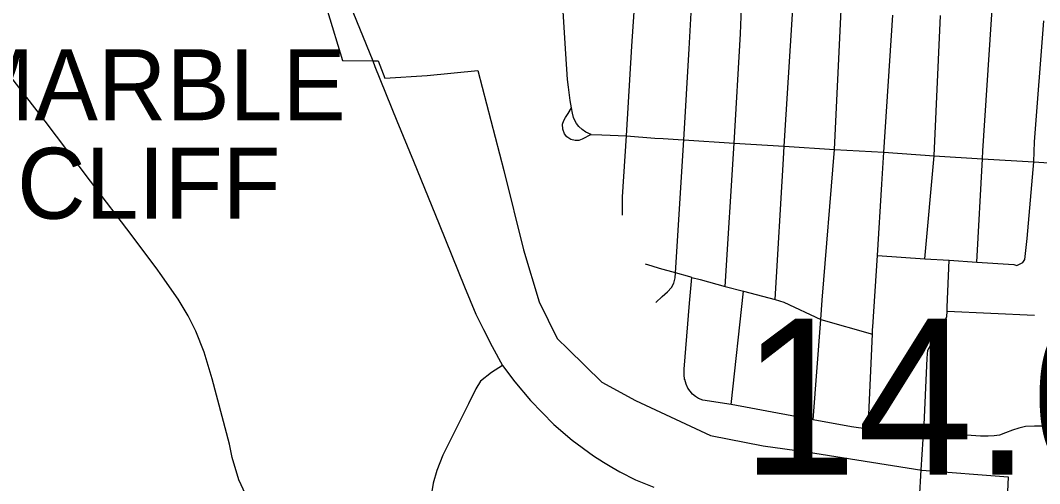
# Model space of a CAD drawing. Extents: x 1659811 to 1934326, y 644115 to 934867.
# Drawn here: x 1807811 to 1814994, y 720077 to 723342 of the extents above; entities that cross this region are included whole.
import ezdxf

# ---------------------------------------------------------------- set-up
doc = ezdxf.new("R2010")
doc.units = 0
for name, color, linetype in [('Default', 7, 'Continuous'), ('GM_X_City_Street', 7, 'Continuous'), ('GM_X_Corporation', 7, 'Continuous'), ('GM_X_Corporation_Text', 7, 'Continuous'), ('GM_X_US_Route', 7, 'Continuous')]:
    doc.layers.add(name, color=color, linetype=linetype)

msp = doc.modelspace()

# ---------------------------------------------------------------- linework, layer by layer
at = {"layer": 'GM_X_City_Street'}
for points in [[(1808795.1, 721558), (1808779, 721580.7), (1808599.2, 721824.2), (1808306, 722208.8), (1807985.2, 722632.1), (1807670.9, 723038.7), (1807377.6, 723432), (1806989.8, 723953.5), (1806147.3, 725108.1), (1805654.1, 725776.1), (1805409.9, 726117.9), (1805269.4, 726309.7), (1805131.2, 726507.4), (1805081.3, 726573.7), (1805021.7, 726645), (1804975, 726686.2)], [(1812486.9, 722499.7), (1812523.3, 723140.4), (1812553.7, 723692.4), (1812540.7, 723725.4), (1812553.7, 723943.3), (1812621.9, 725031.4)], [(1812778.9, 721467.3), (1812841.8, 722477.5), (1812886.3, 723247.8), (1812895.8, 723492.7), (1812895.8, 723524.6), (1812887.8, 723553.2), (1812849.6, 723594.6), (1812836.9, 723621.7), (1812836.9, 723674.2), (1812879, 724155.2), (1812932.6, 725012.8)], [(1811834.1, 722538.8), (1811795.9, 722553.5), (1811769.5, 722571.9), (1811746.4, 722595.2), (1811730.8, 722614.3), (1811718.7, 722637.3), (1811710, 722658.6), (1811701.3, 722688.1), (1811694.3, 722724.5), (1811684.8, 722777.5), (1811672.7, 722872.1), (1811667.4, 722925.9), (1811661.4, 722998), (1811651.8, 723140.4), (1811634.4, 723445), (1811630.1, 723571.7), (1811622.4, 723731.8)], [(1812081.5, 722527.5), (1812120.6, 723161.2), (1812144, 723507.5), (1812154.3, 723685.4)], [(1813129.6, 721374.4), (1813187.9, 722367.3), (1813194.6, 722454.3), (1813268.3, 723648.7)], [(1814552.2, 721638.8), (1814590.7, 722366.3), (1814593.6, 722422), (1814668.9, 723564.4)], [(1813398.7, 720526.3), (1813450.9, 721232.9), (1813462.2, 721369.8), (1813547.3, 722431.1), (1813594.8, 723416.9)], [(1813818.3, 721182), (1813850.4, 721683.9), (1813882.6, 722186.7), (1813897.1, 722412.4), (1813959, 723379.1)], [(1814186, 721662.3), (1814250.3, 722387), (1814294.3, 723376.9)], [(1814875, 721635.5), (1814888.6, 721655.9), (1814905.2, 721804.8), (1814953.4, 722345.2), (1814957.5, 722486.7), (1815023.8, 723337.6)], [(1811834.1, 722538.8), (1811769, 722504.1), (1811747.3, 722495.4), (1811720.4, 722494.5), (1811689.1, 722503.2), (1811663.1, 722521.4), (1811644.9, 722543.1), (1811632.7, 722576.1), (1811631.8, 722610), (1811641.4, 722636), (1811651.8, 722657.7), (1811670.9, 722685.5), (1811694.3, 722724.5)], [(1811834.1, 722538.8), (1811907.9, 722534.4), (1812081.5, 722527.5)], [(1812054.6, 721968.5), (1812054.6, 722099.5), (1812081.5, 722527.5)], [(1812081.5, 722527.5), (1812281.9, 722512.5), (1812341.5, 722508.8)], [(1812341.5, 722508.8), (1812445.6, 722502.3)], [(1812428.2, 721563.7), (1812486.9, 722499.7)], [(1812445.6, 722502.3), (1812486.9, 722499.7), (1812841.8, 722477.5), (1813194.6, 722454.3), (1813547.3, 722431.1), (1813897.1, 722412.4), (1814250.3, 722387), (1814590.7, 722366.3), (1814953.4, 722345.2), (1815345.5, 722319.7)], [(1813850.4, 721683.9), (1814186, 721662.3), (1814355.5, 721651.4), (1814552.2, 721638.8), (1814813.1, 721622), (1814833.4, 721614.4), (1814875, 721635.5)], [(1812428.2, 721563.7), (1812315.3, 721594.1), (1812263.3, 721609.7), (1812216.5, 721622.8)], [(1814172.9, 720390.5), (1814173, 720390.9), (1814178.2, 720440.4), (1814200.4, 720961.2), (1814207.1, 721017.6), (1814299.6, 721182.4), (1814340.1, 721253.6), (1814341.5, 721292.9), (1814342.5, 721319.9), (1814355.5, 721651.4)], [(1809957.5, 719201.3), (1809776.8, 719433.6), (1809579, 719687.3), (1809497.2, 719814.2), (1809436.9, 719925.9), (1809398.2, 720003.3), (1809351.5, 720103.2), (1809303.9, 720261.2), (1809284.4, 720354.3), (1809232.5, 720551.3), (1809163.3, 720815.3), (1809107, 721003.6), (1809048.6, 721150.8), (1808994.5, 721259), (1808923.1, 721378.1), (1808795.1, 721558)], [(1812290.2, 721352.8), (1812333.6, 721396.2), (1812371.8, 721428.3), (1812400.4, 721459.5), (1812416, 721489.9), (1812425.6, 721528.1), (1812428.2, 721563.7)], [(1812529.2, 721534.1), (1812428.2, 721563.7)], [(1812492.6, 720810.6), (1812492.4, 720811.1), (1812489, 720846.7), (1812489, 720884.9), (1812526.3, 721350.1), (1812543.7, 721529.8), (1812529.2, 721534.1)], [(1812543.7, 721529.8), (1812600.9, 721515.9), (1812778.9, 721467.3), (1812906.5, 721432.6), (1813129.6, 721374.4), (1813190.3, 721356.2), (1813450.9, 721232.9), (1813815, 721130.9)], [(1812819.7, 720634), (1812906.5, 721432.6)], [(1814341.5, 721292.9), (1814958, 721263.9)], [(1813785.8, 720462.1), (1813815, 721130.9), (1813817, 721161.8), (1813818.3, 721182)], [(1815022.8, 720483), (1814957.7, 720483), (1814894.3, 720479.1), (1814846.6, 720468.2), (1814803.2, 720453.4), (1814754.6, 720434.4), (1814710.3, 720419.6), (1814673.9, 720413.5), (1814630.5, 720410.9), (1814576.6, 720412.6), (1814178.2, 720440.4), (1813785.8, 720462.1), (1813668.6, 720478.6), (1813398.7, 720526.3), (1812957.7, 720609.7), (1812819.7, 720634), (1812620.9, 720666.1), (1812589.6, 720678.3), (1812569.7, 720690.4), (1812547.1, 720707.8), (1812530.6, 720727.8), (1812514.1, 720750.3), (1812502.8, 720779), (1812492.6, 720810.6)], [(1814158.2, 720174.8), (1814172.9, 720390.5)], [(1814147, 719955.1), (1814147.8, 719967.6), (1814158.2, 720174.8)]]:
    msp.add_lwpolyline(points, dxfattribs=at)
at = {"layer": 'GM_X_Corporation'}
msp.add_lwpolyline([(1809870.1, 723755.9), (1810081.5, 723059.9), (1810294.1, 723056.4), (1810333.2, 723055.8), (1810379.2, 722934.3), (1810677, 722954.2), (1811035.5, 722989), (1811218.4, 722284.4), (1811356.1, 721725), (1811467.7, 721357.8), (1811593.9, 721100.8), (1811670.5, 721025.1), (1811908.3, 720791.5), (1812145.7, 720663.2), (1812674, 720415.4), (1813045.6, 720344.3), (1813351.6, 720300.6), (1814163.1, 720172.6), (1814772.4, 720125.6), (1814739.6, 719391.6)], dxfattribs=at)
at = {"layer": 'GM_X_US_Route'}
for points in [[(1809423.7, 725672.5), (1809490.4, 725538.9), (1809558, 725396.9), (1809595.4, 725307.5), (1809632.7, 725192.1), (1809680.4, 724995), (1809767.2, 724626.1), (1809829.7, 724390), (1809924.4, 724074.9), (1810012.9, 723801.5), (1810133.6, 723453.4), (1810294.1, 723056.4), (1810309.8, 723017.5)], [(1810309.8, 723017.5), (1810464.3, 722633.1), (1810581.5, 722350.1), (1810762, 721904.8), (1810940.9, 721464.7), (1811021.6, 721271.1), (1811074, 721162.9), (1811135.7, 721044), (1811208, 720910.1)], [(1811208, 720910.1), (1811130.5, 720860), (1811054.1, 720798.3), (1811020.2, 720744.5), (1810968.6, 720639.8)], [(1811208, 720910.1), (1811295.4, 720794.9), (1811405.6, 720662.9), (1811569.7, 720493.6), (1811699, 720383.4), (1811851, 720274), (1811921.3, 720228), (1811978.6, 720194.2), (1812036.7, 720160.3), (1812146.1, 720104.8), (1812274.6, 720051.8)], [(1810968.6, 720639.8), (1810924.3, 720550.1), (1810787.6, 720277.5), (1810745.9, 720169), (1810720.8, 720079.6), (1810706.9, 719992.8), (1810697.3, 719915.5), (1810696.4, 719825.2), (1810700.8, 719760.1), (1810709.5, 719703.7), (1810717.3, 719656), (1810730.3, 719604.8), (1810745.1, 719554.4), (1810769.3, 719492.7), (1810798.9, 719428.5), (1810844.9, 719346.1), (1810903.9, 719262.7), (1811006.4, 719146.4), (1811154.8, 718969.3), (1811246.3, 718871.7), (1811358.8, 718748), (1811428.8, 718661.7)]]:
    msp.add_lwpolyline(points, dxfattribs=at)

# ---------------------------------------------------------------- texts
at = {"layer": 'Default'}
msp.add_text('14.00', height=1100, dxfattribs=at).set_placement((1812891.1, 720139.9))
at = {"layer": 'GM_X_Corporation_Text'}
for s, p in [('MARBLE', (1807354.2, 722638.2)), ('CLIFF', (1807787.6, 721944.1))]:
    msp.add_text(s, height=500, rotation=0.00001, dxfattribs=at).set_placement(p)

doc.saveas('drawing.dxf')
